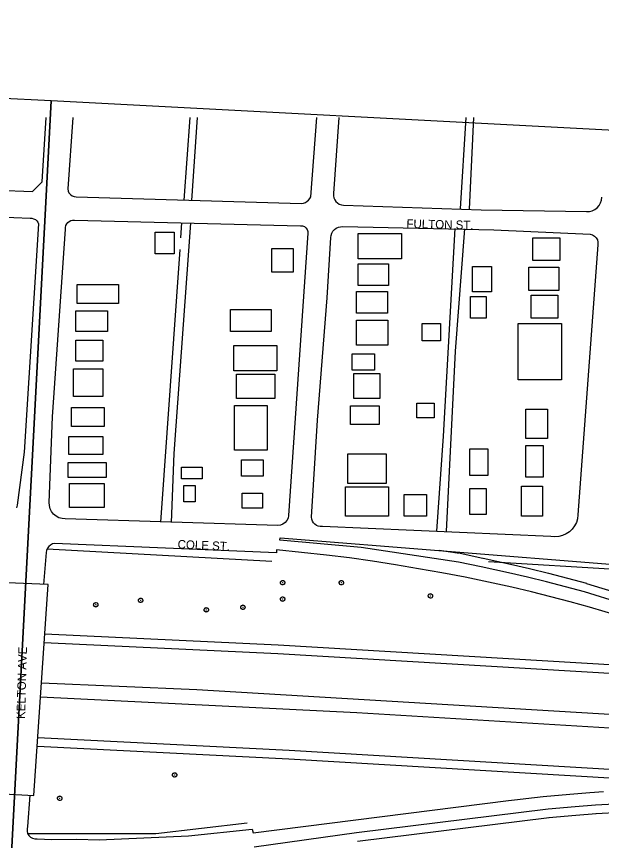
# Model space of a CAD drawing. Extents: x -9648 to 41057, y -12373 to 40276.
# Drawn here: x 15887 to 16567, y -5297 to -4339 of the extents above; entities that cross this region are included whole.
import ezdxf

# ---------------------------------------------------------------- set-up
doc = ezdxf.new("R2010")
doc.units = 0
for name, color, linetype in [('Default', 7, 'Continuous'), ('SC_Scratch1', 7, 'Continuous'), ('SH_Data', 7, 'Continuous')]:
    doc.layers.add(name, color=color, linetype=linetype)

# ---------------------------------------------------------------- blocks, each defined once
blk = doc.blocks.new('15_PIN')
at = {"layer": 'Default'}
for p, q in [((-2.8, 0), (2.8, 0)), ((0, 2.8), (0, -2.8))]:
    blk.add_line(p, q, dxfattribs=at)
for centre, start, end in [((-25.5, 4.5), 275.99002, 64.00998), ((-25.9, -1.5), 289.32335, 77.34332), ((-23.8, 10.3), 262.65669, 50.67665), ((-20.8, 15.5), 249.32335, 37.34332), ((-16.7, 19.8), 235.99002, 24.00998), ((-11.6, 23.2), 222.65669, 10.67665), ((-6, 25.2), 209.32335, 357.34332), ((0, 25.9), 195.99002, 344.00998), ((6, 25.2), 182.65669, 330.67665), ((11.6, 23.2), 169.32335, 317.34332), ((16.7, 19.8), 155.99002, 304.00998), ((20.8, 15.5), 142.65669, 290.67665), ((23.8, 10.3), 129.32335, 277.34332), ((25.5, 4.5), 115.99002, 264.00998), ((25.9, -1.5), 102.65669, 250.67665), ((-24.8, -7.4), 302.65669, 90.67665), ((-22.4, -13), 315.99002, 104.00998), ((-18.8, -17.8), 329.32335, 117.34332), ((-14.2, -21.6), 342.65669, 130.67665), ((-8.9, -24.3), 355.99002, 144.00998), ((-3, -25.7), 9.32335, 157.34332), ((3, -25.7), 22.65669, 170.67665), ((8.9, -24.3), 35.99002, 184.00998), ((14.2, -21.6), 49.32335, 197.34332), ((18.8, -17.8), 62.65669, 210.67665), ((22.4, -13), 75.99002, 224.00998), ((24.8, -7.4), 89.32335, 237.34332)]:
    blk.add_arc(centre, 3.05, start, end, dxfattribs=at)

msp = doc.modelspace()

# ---------------------------------------------------------------- linework, layer by layer
at = {"layer": 'SC_Scratch1'}
for p, q in [((15927.4, -4436.94), (14069.83, -4338.81)), ((15927.4, -4436.94), (15846.16, -5974.79)), ((15846.16, -5974.79), (15927.4, -4436.94)), ((17512.22, -4520.66), (15927.4, -4436.94))]:
    msp.add_line(p, q, dxfattribs=at)
at = {"layer": 'SH_Data'}
for p, q in [((15917.08, -4530.86), (15921.68, -4456.26)), ((15952.48, -4456.26), (15946.68, -4539.26)), ((16088.68, -4456.26), (16081.68, -4552.36)), ((16091.08, -4552.66), (16097.48, -4456.26)), ((16229.28, -4548.26), (16236.28, -4456.26)), ((16261.88, -4456.26), (16255.68, -4544.66)), ((16409.48, -4456.26), (16403.08, -4562.46)), ((16413.88, -4562.96), (16418.68, -4456.26)), ((15355.98, -4522.86), (15905.88, -4542.26)), ((15905.88, -4542.26), (15917.08, -4530.86)), ((15946.68, -4539.26), (15947.18, -4541.66)), ((15947.18, -4541.66), (15948.18, -4543.96)), ((15948.18, -4543.96), (15949.78, -4545.86)), ((15949.78, -4545.86), (15951.88, -4547.26)), ((15951.88, -4547.26), (15954.18, -4548.06)), ((15954.18, -4548.06), (15956.68, -4548.26)), ((15956.68, -4548.26), (16218.48, -4556.06)), ((16228.18, -4550.36), (16229.28, -4548.26)), ((16255.68, -4544.66), (16255.68, -4547.16)), ((16255.68, -4547.16), (16256.08, -4549.56)), ((16256.08, -4549.56), (16257.08, -4551.86)), ((16567.18, -4552.26), (16567.48, -4548.86)), ((15354.08, -4552.86), (15902.88, -4573.26)), ((16218.48, -4556.06), (16220.78, -4555.66)), ((16220.78, -4555.66), (16222.98, -4554.86)), ((16222.98, -4554.86), (16224.98, -4553.66)), ((16224.98, -4553.66), (16226.78, -4552.16)), ((16226.78, -4552.16), (16228.18, -4550.36)), ((16257.08, -4551.86), (16258.48, -4553.86)), ((16258.48, -4553.86), (16260.28, -4555.56)), ((16260.28, -4555.56), (16262.38, -4556.86)), ((16262.38, -4556.86), (16264.78, -4557.76)), ((16264.78, -4557.76), (16267.18, -4558.06)), ((16267.18, -4558.06), (16427.48, -4563.66)), ((16562.28, -4561.06), (16564.48, -4558.46)), ((16564.48, -4558.46), (16566.18, -4555.56)), ((16566.18, -4555.56), (16567.18, -4552.26)), ((16427.48, -4563.66), (16549.68, -4565.46)), ((16549.68, -4565.46), (16553.08, -4565.36)), ((16553.08, -4565.36), (16556.38, -4564.56)), ((16556.38, -4564.56), (16559.48, -4563.16)), ((16559.48, -4563.16), (16562.28, -4561.06)), ((15902.88, -4573.26), (15905.08, -4573.26)), ((15905.08, -4573.26), (15907.08, -4573.86)), ((15907.08, -4573.86), (15909.08, -4574.86)), ((15909.08, -4574.86), (15910.68, -4576.16)), ((15910.68, -4576.16), (15911.98, -4577.86)), ((15911.98, -4577.86), (15912.88, -4579.86)), ((15945.58, -4579.96), (15946.88, -4578.26)), ((15946.88, -4578.26), (15948.48, -4576.96)), ((15948.48, -4576.96), (15950.38, -4576.06)), ((15950.38, -4576.06), (15952.38, -4575.46)), ((15952.38, -4575.46), (15954.48, -4575.46)), ((15954.48, -4575.46), (16217.28, -4582.26)), ((15912.88, -4579.86), (15895.88, -4845.06)), ((15928.88, -4804.26), (15944.28, -4586.06)), ((15944.28, -4583.96), (15944.68, -4581.86)), ((15944.28, -4586.06), (15944.28, -4583.96)), ((15944.68, -4581.86), (15945.58, -4579.96)), ((16070.28, -4846.66), (16089.68, -4579.06)), ((16079.08, -4578.76), (16077.98, -4596.26)), ((16217.28, -4582.26), (16219.58, -4582.26)), ((16219.58, -4582.26), (16221.78, -4583.06)), ((16221.78, -4583.06), (16223.68, -4584.46)), ((16223.68, -4584.46), (16224.98, -4586.36)), ((16224.98, -4586.36), (16225.68, -4588.56)), ((16254.98, -4588.46), (16256.68, -4586.46)), ((16256.68, -4586.46), (16258.88, -4584.86)), ((16258.88, -4584.86), (16261.28, -4583.76)), ((16261.28, -4583.76), (16263.88, -4583.16)), ((16263.88, -4583.16), (16266.48, -4583.06)), ((16266.48, -4583.06), (16442.08, -4586.86)), ((16396.88, -4585.36), (16383.08, -4826.46)), ((16397.48, -4727.66), (16408.28, -4585.76)), ((16442.08, -4586.86), (16554.08, -4591.66)), ((16225.68, -4590.86), (16203.48, -4918.86)), ((16225.68, -4588.56), (16225.68, -4590.86)), ((16248.48, -4665.86), (16252.48, -4595.86)), ((16252.48, -4595.86), (16252.78, -4593.26)), ((16252.78, -4593.26), (16253.68, -4590.76)), ((16253.68, -4590.76), (16254.98, -4588.46)), ((16554.08, -4591.66), (16556.78, -4592.56)), ((16556.78, -4592.56), (16559.08, -4594.06)), ((16559.08, -4594.06), (16560.98, -4596.06)), ((16560.98, -4596.06), (16562.38, -4598.56)), ((16563.08, -4604.06), (16539.88, -4918.06)), ((16562.38, -4598.56), (16563.08, -4601.26)), ((16563.08, -4601.26), (16563.08, -4604.06)), ((16077.08, -4609.76), (16054.68, -4926.56)), ((16237.08, -4807.86), (16248.48, -4665.86)), ((16387.08, -4937.56), (16397.48, -4727.66)), ((15925.28, -4903.66), (15928.88, -4804.26)), ((16230.08, -4920.66), (16237.08, -4807.86)), ((16383.08, -4826.46), (16375.28, -4936.96)), ((15895.88, -4845.06), (15888.08, -4906.86)), ((16067.48, -4926.96), (16070.28, -4846.66)), ((15925.38, -4907.36), (15925.28, -4903.66)), ((15888.08, -4906.86), (15887.08, -4909.76)), ((15926.28, -4911.06), (15925.38, -4907.36)), ((15927.98, -4914.36), (15926.28, -4911.06)), ((15930.28, -4917.36), (15927.98, -4914.36)), ((15933.18, -4919.76), (15930.28, -4917.36)), ((15936.48, -4921.46), (15933.18, -4919.76)), ((15940.18, -4922.46), (15936.48, -4921.46)), ((15943.88, -4922.66), (15940.18, -4922.46)), ((16190.88, -4930.46), (15943.88, -4922.66)), ((16202.78, -4921.96), (16201.48, -4924.76)), ((16203.48, -4918.86), (16202.78, -4921.96)), ((16230.28, -4923.06), (16230.08, -4920.66)), ((16231.08, -4925.26), (16230.28, -4923.06)), ((16539.28, -4922.56), (16537.98, -4926.86)), ((16539.88, -4918.06), (16539.28, -4922.56)), ((16193.98, -4930.06), (16190.88, -4930.46)), ((16196.88, -4928.96), (16193.98, -4930.06)), ((16199.38, -4927.06), (16196.88, -4928.96)), ((16201.48, -4924.76), (16199.38, -4927.06)), ((16232.28, -4927.26), (16231.08, -4925.26)), ((16233.88, -4929.06), (16232.28, -4927.26)), ((16235.78, -4930.36), (16233.88, -4929.06)), ((16237.98, -4931.36), (16235.78, -4930.36)), ((16240.28, -4931.76), (16237.98, -4931.36)), ((16242.68, -4931.66), (16240.28, -4931.76)), ((16508.48, -4943.06), (16242.68, -4931.66)), ((16535.88, -4930.96), (16533.18, -4934.56)), ((16537.98, -4926.86), (16535.88, -4930.96)), ((16521.88, -4942.06), (16517.48, -4943.16)), ((16526.08, -4940.16), (16521.88, -4942.06)), ((16529.88, -4937.66), (16526.08, -4940.16)), ((16533.18, -4934.56), (16529.88, -4937.66)), ((15931.48, -4951.26), (15928.98, -4951.96)), ((16189.28, -4962.06), (15931.48, -4951.26)), ((16193.08, -4947.46), (16193.48, -4944.86)), ((16287.88, -4956.06), (16193.08, -4947.46)), ((16193.48, -4944.86), (16582.08, -4975.66)), ((16512.98, -4943.46), (16508.48, -4943.06)), ((16517.48, -4943.16), (16512.98, -4943.46)), ((15921.98, -4959.36), (15921.48, -4961.86)), ((15923.08, -4956.96), (15921.98, -4959.36)), ((15922.79, -4957.58), (16183.85, -4971.86)), ((15924.68, -4954.86), (15923.08, -4956.96)), ((15926.68, -4953.16), (15924.68, -4954.86)), ((15928.98, -4951.96), (15926.68, -4953.16)), ((16247.48, -4964.86), (16189.28, -4958.86)), ((16189.28, -4958.86), (16189.28, -4962.06)), ((16400.78, -4972.96), (16287.88, -4956.06)), ((16402.26, -4963.07), (16378.65, -4959.54)), ((15921.48, -4961.86), (15918.48, -4998.86)), ((16274.28, -4968.16), (16247.48, -4964.86)), ((16300.98, -4971.86), (16274.28, -4968.16)), ((16429.34, -4968.78), (16402.84, -4963.18)), ((16461.25, -4975.9), (16429.45, -4968.8)), ((16461.25, -4975.9), (16429.45, -4968.8)), ((16327.68, -4976.06), (16300.98, -4971.86)), ((16354.28, -4980.66), (16327.68, -4976.06)), ((16427.28, -4978.56), (16400.78, -4972.96)), ((16459.08, -4985.66), (16427.28, -4978.56)), ((16435.85, -4972.35), (16680.32, -4987.24)), ((16483.43, -4980.8), (16461.23, -4975.9)), ((16381.58, -4985.46), (16354.28, -4980.66)), ((16408.88, -4990.66), (16381.58, -4985.46)), ((16481.28, -4990.56), (16459.08, -4985.66)), ((16505.71, -4986.14), (16483.61, -4980.84)), ((16527.88, -4991.88), (16505.88, -4986.18)), ((15924.08, -4999.06), (15876.48, -4997.26)), ((15907.28, -5244.26), (15924.08, -4999.06)), ((16435.98, -4996.26), (16408.88, -4990.66)), ((16463.08, -5002.26), (16435.98, -4996.26)), ((16503.38, -4995.86), (16481.28, -4990.56)), ((16525.38, -5001.56), (16503.38, -4995.86)), ((16549.96, -4998.03), (16528.06, -4991.93)), ((16698.01, -5043.5), (16550.21, -4998.1)), ((16485.78, -5007.66), (16463.08, -5002.26)), ((16508.28, -5013.26), (16485.78, -5007.66)), ((16547.28, -5007.66), (16525.38, -5001.56)), ((16695.08, -5053.06), (16547.28, -5007.66)), ((16530.88, -5019.26), (16508.28, -5013.26)), ((16553.28, -5025.46), (16530.88, -5019.26)), ((16735.68, -5079.46), (16553.28, -5025.46)), ((15919.95, -5056.27), (16191.35, -5069.07)), ((15919.48, -5066.26), (16190.88, -5079.06)), ((16191.47, -5069.08), (16868.97, -5109.73)), ((16190.88, -5079.06), (16960.88, -5125.26)), ((16096.88, -5121.66), (15916.18, -5113.86)), ((17046.08, -5177.66), (16096.88, -5121.66)), ((16282.88, -5148.06), (15915.08, -5130.06)), ((17046.08, -5194.26), (16282.88, -5148.06)), ((15911.88, -5176.86), (16204.28, -5191.66)), ((15911.37, -5186.85), (16203.77, -5201.65)), ((16204.28, -5191.66), (16983.68, -5237.56)), ((16203.69, -5201.64), (16945.21, -5245.31)), ((15859.88, -5241.86), (15907.28, -5244.26)), ((15902.48, -5244.06), (15900.08, -5280.26)), ((16469.38, -5248.96), (16479.38, -5247.76)), ((16479.38, -5247.76), (16489.48, -5246.56)), ((16489.48, -5246.56), (16499.58, -5245.26)), ((16499.58, -5245.26), (16530.38, -5242.56)), ((16530.38, -5242.56), (16553.48, -5240.86)), ((16553.48, -5240.86), (16569.68, -5239.46)), ((16162.08, -5287.86), (16459.28, -5250.06)), ((16459.28, -5250.06), (16469.38, -5248.96)), ((16536.48, -5257.46), (16505.28, -5260.26)), ((16560.18, -5255.46), (16536.48, -5257.46)), ((16595.48, -5253.76), (16560.18, -5255.46)), ((16505.28, -5260.26), (16282.28, -5287.66)), ((16537.37, -5267.42), (16506.17, -5270.22)), ((16561.02, -5265.43), (16537.32, -5267.43)), ((16595.96, -5263.75), (16560.66, -5265.45)), ((16048.94, -5288.61), (16155.35, -5276.13)), ((16506.5, -5270.19), (16283.5, -5297.59)), ((15900.08, -5280.26), (15899.38, -5282.96)), ((15899.38, -5282.96), (15899.38, -5285.66)), ((15899.38, -5285.66), (15900.08, -5288.36)), ((16087.28, -5291.26), (16161.28, -5283.26)), ((16161.28, -5283.26), (16162.08, -5287.86)), ((15900.08, -5288.36), (15901.48, -5290.66)), ((15900.23, -5288.61), (16048.94, -5288.61)), ((15901.48, -5290.66), (15903.48, -5292.66)), ((15903.48, -5292.66), (15905.88, -5293.96)), ((15905.88, -5293.96), (15908.48, -5294.66)), ((15908.48, -5294.66), (15911.28, -5294.66)), ((15911.28, -5294.66), (15928.08, -5295.26)), ((15928.08, -5295.26), (15957.48, -5295.06)), ((15957.48, -5295.06), (15983.08, -5295.66)), ((15983.08, -5295.66), (16087.28, -5291.26)), ((16282.28, -5287.66), (16163.28, -5304.26))]:
    msp.add_line(p, q, dxfattribs=at)
for points in [[(16048.34, -4589.46), (16070.45, -4589.46), (16070.45, -4614.73), (16048.34, -4614.73)], [(16284.28, -4590.93), (16334.72, -4590.93), (16334.72, -4620.58), (16284.28, -4620.58)], [(16487.3, -4595.98), (16518.82, -4595.98), (16518.82, -4622.47), (16487.3, -4622.47)], [(16184.15, -4608.41), (16208.62, -4608.41), (16208.62, -4636.06), (16184.15, -4636.06)], [(16284.28, -4626.25), (16319.59, -4626.25), (16319.59, -4651.48), (16284.28, -4651.48)], [(16417.31, -4629.41), (16439.38, -4629.41), (16439.38, -4659.05), (16417.31, -4659.05)], [(16482.88, -4630.04), (16517.56, -4630.04), (16517.56, -4657.16), (16482.88, -4657.16)], [(15957.53, -4650.28), (16005.7, -4650.28), (16005.7, -4672.39), (15957.53, -4672.39)], [(16282.39, -4658.42), (16318.33, -4658.42), (16318.33, -4683.65), (16282.39, -4683.65)], [(16414.79, -4664.09), (16433.08, -4664.09), (16433.08, -4689.32), (16414.79, -4689.32)], [(16485.41, -4662.83), (16516.3, -4662.83), (16516.3, -4689.32), (16485.41, -4689.32)], [(15955.95, -4681.08), (15993.07, -4681.08), (15993.07, -4704.78), (15955.95, -4704.78)], [(16135.98, -4679.5), (16183.36, -4679.5), (16183.36, -4704.78), (16135.98, -4704.78)], [(16282.39, -4691.84), (16318.96, -4691.84), (16318.96, -4720.86), (16282.39, -4720.86)], [(16358.68, -4695.63), (16380.11, -4695.63), (16380.11, -4715.81), (16358.68, -4715.81)], [(16470.27, -4695.63), (16520.71, -4695.63), (16520.71, -4761.22), (16470.27, -4761.22)], [(15955.95, -4715.05), (15987.54, -4715.05), (15987.54, -4739.53), (15955.95, -4739.53)], [(16139.93, -4721.36), (16189.67, -4721.36), (16189.67, -4750.59), (16139.93, -4750.59)], [(16277.35, -4730.95), (16303.2, -4730.95), (16303.2, -4749.87), (16277.35, -4749.87)], [(15953.59, -4748.22), (15987.54, -4748.22), (15987.54, -4780.6), (15953.59, -4780.6)], [(16143.09, -4754.54), (16187.31, -4754.54), (16187.31, -4782.97), (16143.09, -4782.97)], [(16279.24, -4753.65), (16309.5, -4753.65), (16309.5, -4782.66), (16279.24, -4782.66)], [(16352.37, -4788.34), (16372.55, -4788.34), (16372.55, -4805.37), (16352.37, -4805.37)], [(15951.22, -4793.24), (15989.12, -4793.24), (15989.12, -4815.36), (15951.22, -4815.36)], [(16140.72, -4790.87), (16178.62, -4790.87), (16178.62, -4843), (16140.72, -4843)], [(16275.45, -4791.49), (16308.87, -4791.49), (16308.87, -4812.94), (16275.45, -4812.94)], [(16479.1, -4795.28), (16504.32, -4795.28), (16504.32, -4829.34), (16479.1, -4829.34)], [(15948.06, -4827.2), (15987.54, -4827.2), (15987.54, -4847.74), (15948.06, -4847.74)], [(16414.16, -4841.32), (16434.97, -4841.32), (16434.97, -4872.22), (16414.16, -4872.22)], [(16479.1, -4837.54), (16499.28, -4837.54), (16499.28, -4874.12), (16479.1, -4874.12)], [(16148.62, -4854.06), (16173.88, -4854.06), (16173.88, -4873.02), (16148.62, -4873.02)], [(16272.3, -4847), (16317.07, -4847), (16317.07, -4881.68), (16272.3, -4881.68)], [(15947.27, -4857.22), (15991.49, -4857.22), (15991.49, -4874.6), (15947.27, -4874.6)], [(16079.13, -4862.75), (16102.82, -4862.75), (16102.82, -4876.18), (16079.13, -4876.18)], [(15948.85, -4881.7), (15989.12, -4881.7), (15989.12, -4909.35), (15948.85, -4909.35)], [(16081.5, -4884.07), (16094.92, -4884.07), (16094.92, -4903.03), (16081.5, -4903.03)], [(16149.41, -4892.76), (16173.09, -4892.76), (16173.09, -4910.14), (16149.41, -4910.14)], [(16269.78, -4885.47), (16319.59, -4885.47), (16319.59, -4919.53), (16269.78, -4919.53)], [(16337.87, -4894.3), (16363.72, -4894.3), (16363.72, -4919.53), (16337.87, -4919.53)], [(16414.16, -4887.36), (16433.08, -4887.36), (16433.08, -4917.63), (16414.16, -4917.63)], [(16474.06, -4884.84), (16498.65, -4884.84), (16498.65, -4919.53), (16474.06, -4919.53)]]:
    msp.add_lwpolyline(points, close=True, dxfattribs=at)

# ---------------------------------------------------------------- block references
at = {"layer": 'SH_Data', "xscale": 0.10639346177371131, "yscale": 0.10639346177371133, "rotation": 64.61472397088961}
for p in [(16196.57, -4996.9), (16264.82, -4996.9), (16368.3, -5012.32), (16031.45, -5017.45), (16196.57, -5015.99), (15979.34, -5022.59), (16107.77, -5028.47), (16150.34, -5025.53), (16070.94, -5220.36), (15937.38, -5247.52)]:
    msp.add_blockref('15_PIN', p, dxfattribs=at)

# ---------------------------------------------------------------- texts
at = {"layer": 'SC_Scratch1'}
for s, rotation, p in [('FULTON ST.', 358.76035, (16340.41, -4584.59)), ('COLE ST.', 357.60107, (16074.28, -4957.17)), ('KELTON AVE', 88.50218, (15897.14, -5155.43))]:
    msp.add_text(s, height=10, rotation=rotation, dxfattribs=at).set_placement(p)

doc.saveas('drawing.dxf')
